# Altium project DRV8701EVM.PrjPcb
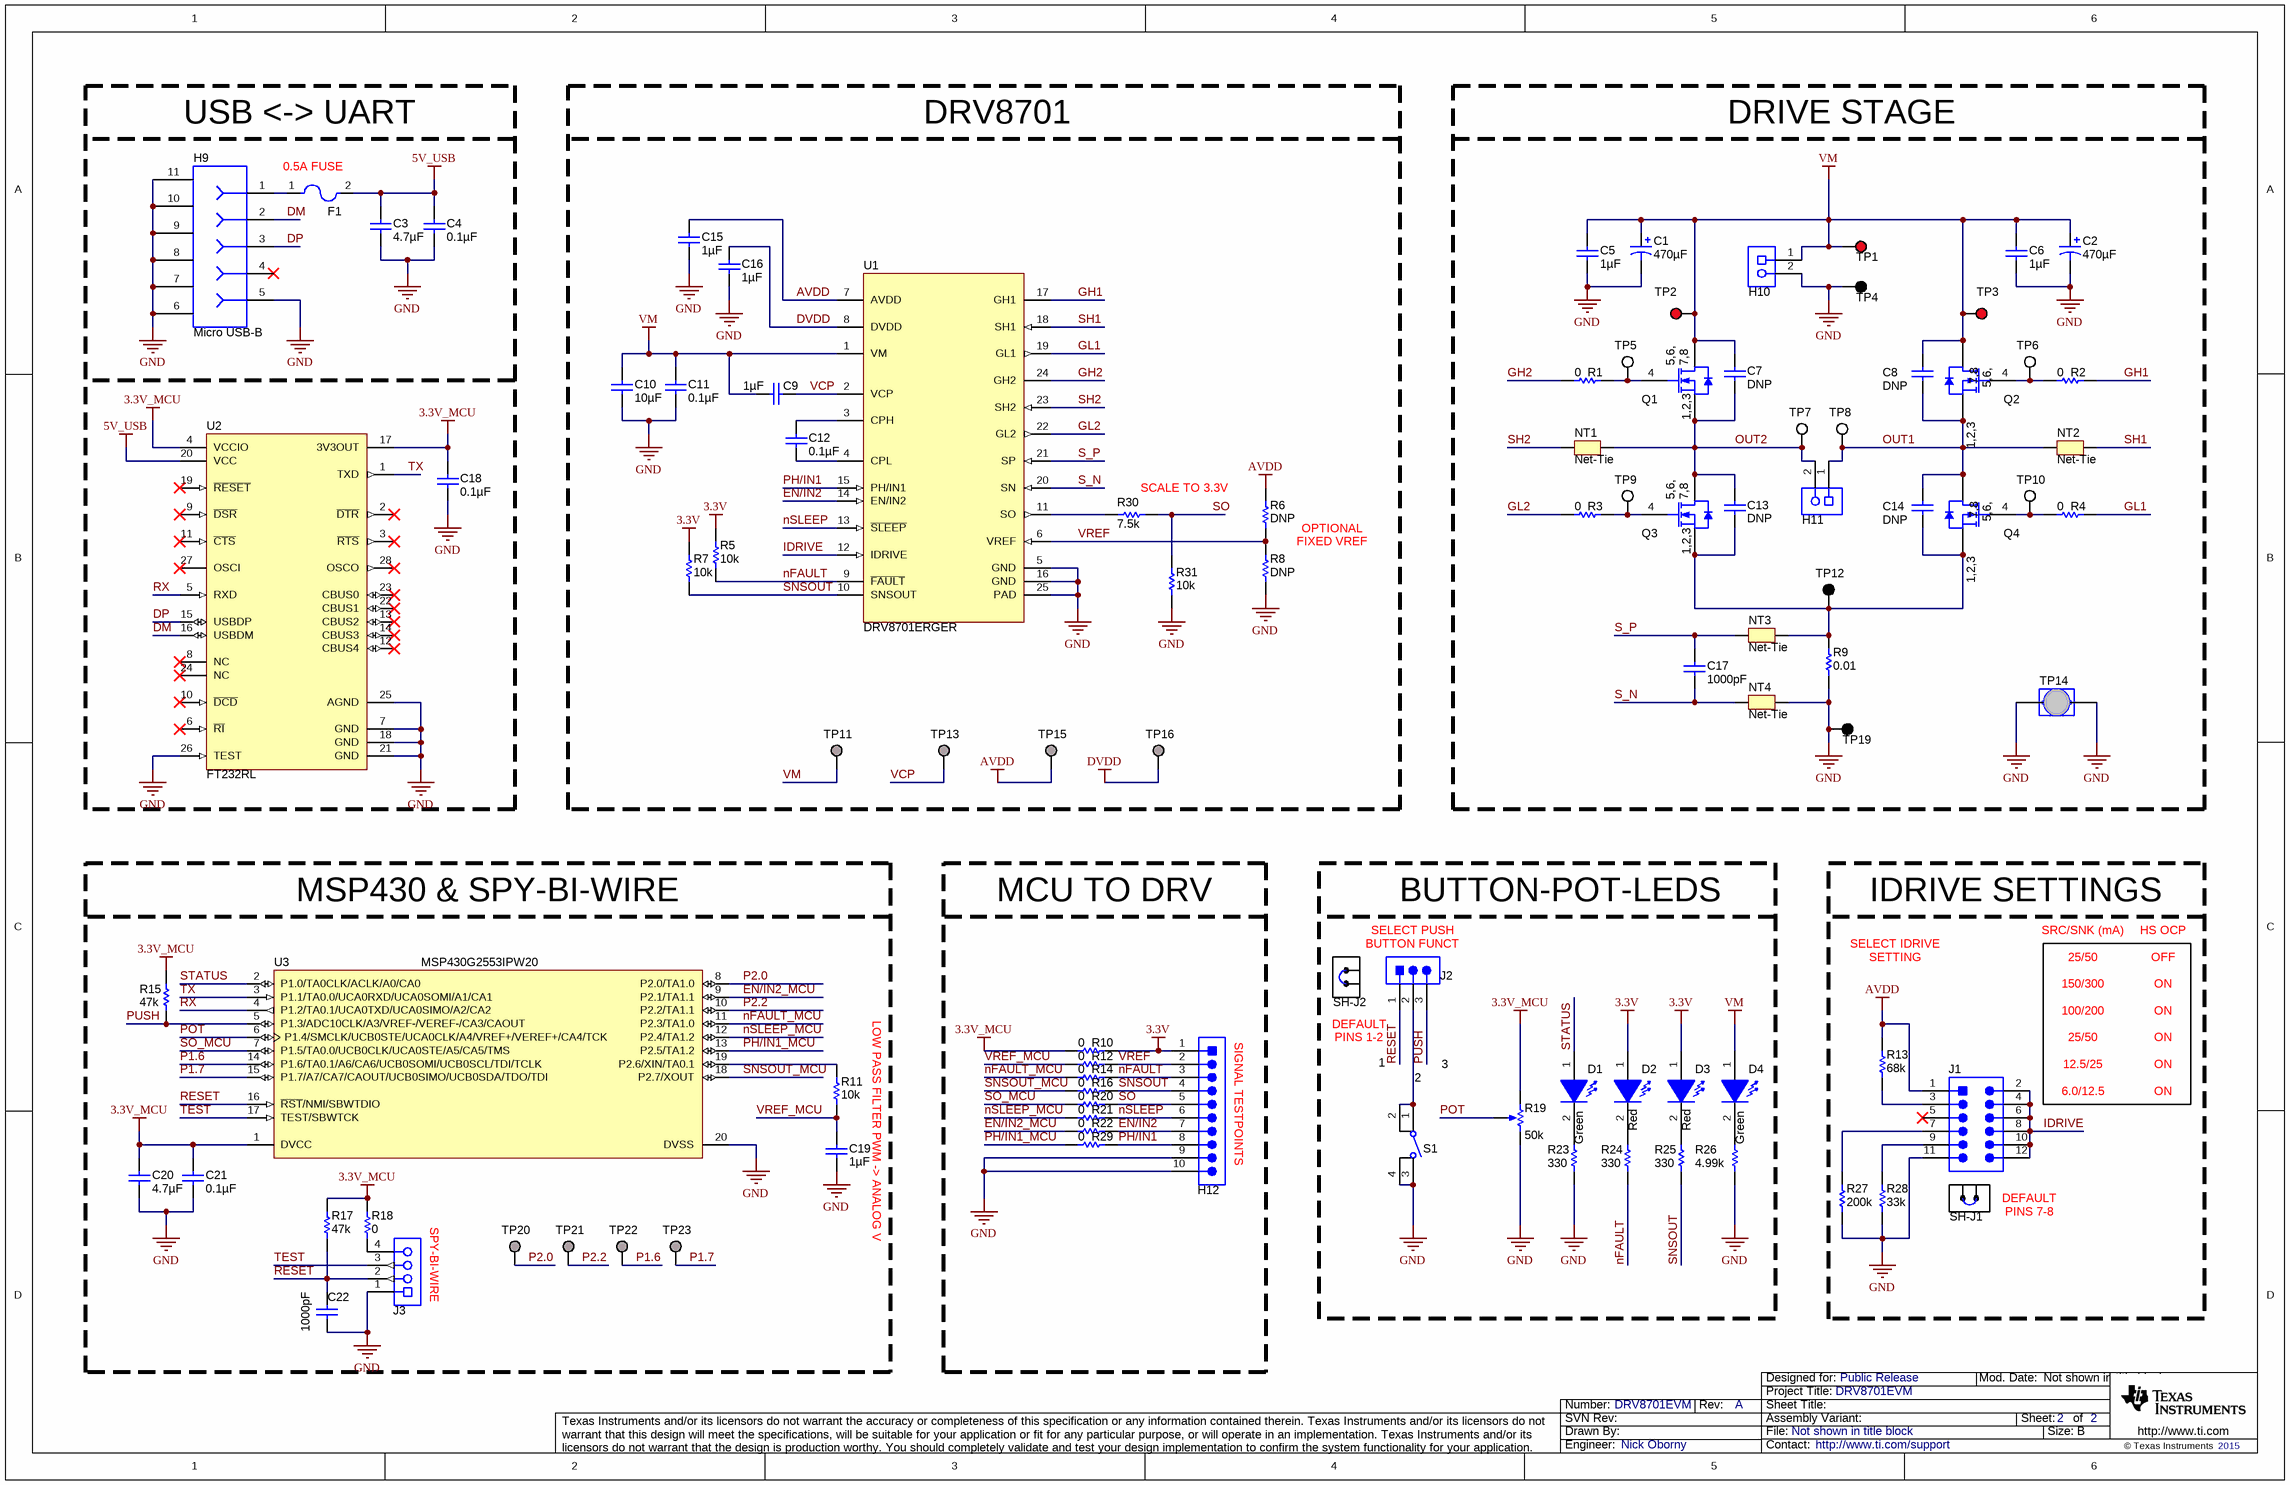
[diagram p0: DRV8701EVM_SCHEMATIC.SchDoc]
CopyrightYear: 2015; PCB_Layout: Nick Oborny; PCB_Rev: A; PRJ_Customer: Public Release; PRJ_Engineer: Nick Oborny; PRJ_Number: DRV8701EVM; PRJ_Title: DRV8701EVM; SCH_Rev: A; TechSupport: http://www.ti.com/support
2 sheets, 119 parts. Net scope: global (net labels, ports and power ports of the same name join across sheets).
Board file: DRV8701EVM.PcbDoc
Sheets:
  DRV8701EVM_SCHEMATIC.SchDoc
  DRV8701EVM_HARDWARE.SchDoc

## Sheet DRV8701EVM_SCHEMATIC.SchDoc
size 431 x 279 mm; Date: Not shown in title block; ApprovedBy: Not shown in title block; CheckedBy: Not shown in title block; Author: Not shown in title block; CompanyName: Not shown in title block; Engineer: Not shown in title block; Organization: Not shown in title block; Address1: Not shown in title block; Address2: Not shown in title block; Address3: Not shown in title block; Address4: Not shown in title block; DocumentNumber: 1; Revision: Use project parameter SCH_Rev; SheetNumber: 2; SheetTotal: 2; PageSetup: Record=PageOptions¦CenterHorizontal=True¦CenterVertical=True¦PrintScale=0.62¦XCorrection=1.00¦YCorrection=1.00¦PrintKind=0¦BorderSize=5000000¦LeftOffset=0¦BottomOffset=0¦Orientation=2¦PaperLength=1000¦PaperWidth=1000¦Scale=100¦PaperSource=15¦PrintQuality=600¦MediaType=1¦DitherType=10¦PaperKind=Letter¦PrintScaleMode=1

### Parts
C1  ValueDisplayed: 470µF  [M_1000x2000]  (hidden comment: ECA-1HM471)
C2  ValueDisplayed: 470µF  [M_1000x2000]  (hidden comment: ECA-1HM471)
C3  ValueDisplayed: 4.7µF  [0805L]  (hidden comment: C2012X7R1A475M)
C4  ValueDisplayed: 0.1µF  [0603L]  (hidden comment: C0603C104K8RACTU)
C5  ValueDisplayed: 1µF  [0805L]  (hidden comment: GRM21BR71H105KA12L)
C6  ValueDisplayed: 1µF  [0805L]  (hidden comment: GRM21BR71H105KA12L)
C7  DNP  [0603L]
C8  DNP  [0603L]
C9  ValueDisplayed: 1µF  [0603L]  (hidden comment: C1608X7R1C105K)
C10  ValueDisplayed: 10µF  [1210L]  (hidden comment: GRM32ER71H106KA12L)
C11  ValueDisplayed: 0.1µF  [0603L]  (hidden comment: C1608X7R1H104K)
C12  ValueDisplayed: 0.1µF  [0603L]  (hidden comment: C1608X7R1H104K)
C13  DNP  [0603L]
C14  DNP  [0603L]
C15  ValueDisplayed: 1µF  [0603L]  (hidden comment: GRM188R70J105KA01D)
C16  ValueDisplayed: 1µF  [0603L]  (hidden comment: GRM188R70J105KA01D)
C17  ValueDisplayed: 1000pF  [0402L]  (hidden comment: GRM155R71C102KA01D)
C18  ValueDisplayed: 0.1µF  [0603L]  (hidden comment: C0603C104K8RACTU)
C19  ValueDisplayed: 1µF  [0603L]  (hidden comment: GRM188R70J105KA01D)
C20  ValueDisplayed: 4.7µF  [0805L]  (hidden comment: C2012X7R1A475M)
C21  ValueDisplayed: 0.1µF  [0603L]  (hidden comment: C0603C104K8RACTU)
C22  ValueDisplayed: 1000pF  [0603L]  (hidden comment: GRM188R71C102KA01D)
D1  value Green  [LED_LTST-C171]  (hidden comment: LTST-C171GKT)
D2  value Red  [LED_LTST-C170]  (hidden comment: LTST-C170KRKT)
D3  value Red  [LED_LTST-C170]  (hidden comment: LTST-C170KRKT)
D4  value Green  [LED_LTST-C171]  (hidden comment: LTST-C171GKT)
F1  1206L050/15YR  [1206_FUSE]  (value not drawn)
H9  PackageReference: Micro USB-B  [CONN_USB_micro_ZX62-B-5PA]  (hidden comment: ZX62-B-5PA(11))
H10  691 101 710 002  [Wurth_691101710002]  (value not drawn)
H11  691 101 710 002  [Wurth_691101710002]  (value not drawn)
H12  TSW-110-07-G-S  [TSW-110-07-G-S]  (value not drawn)
J1  PEC06DAAN  [CONN_PEC06DAAN]  (value not drawn)
J2  PEC03SAAN  [CONN_PEC03SAAN]  (value not drawn)
J3  851-43-004-20-001000  [CONN_851-43-004-20-001000]  (value not drawn)
NT1  Net-Tie  [Net-Tie_10mil]  (net tie, no BOM)
NT2  Net-Tie  [Net-Tie_10mil]  (net tie, no BOM)
NT3  Net-Tie  [Net-Tie_10mil]  (net tie, no BOM)
NT4  Net-Tie  [Net-Tie_10mil]  (net tie, no BOM)
Q1  CSD18532Q5B  [TRANS_NexFET_Q5B]  (value not drawn)
Q2  CSD18532Q5B  [TRANS_NexFET_Q5B]  (value not drawn)
Q3  CSD18532Q5B  [TRANS_NexFET_Q5B]  (value not drawn)
Q4  CSD18532Q5B  [TRANS_NexFET_Q5B]  (value not drawn)
R1  value 0  [0603L]  (hidden comment: CRCW06030000Z0EA)
R2  value 0  [0603L]  (hidden comment: CRCW06030000Z0EA)
R3  value 0  [0603L]  (hidden comment: CRCW06030000Z0EA)
R4  value 0  [0603L]  (hidden comment: CRCW06030000Z0EA)
R5  value 10k  [0603L]  (hidden comment: CRCW060310K0JNEA)
R6  DNP  [0603L]
R7  value 10k  [0603L]  (hidden comment: CRCW060310K0JNEA)
R8  DNP  [0603L]
R9  value 0.01  [2512M]  (hidden comment: CRA2512-FZ-R010ELF)
R10  value 0  [0603L]  (hidden comment: CRCW06030000Z0EA)
R11  value 10k  [0603L]  (hidden comment: CRCW060310K0JNEA)
R12  value 0  [0603L]  (hidden comment: CRCW06030000Z0EA)
R13  value 68k  [0603L]  (hidden comment: CRCW060368K0JNEA)
R14  value 0  [0603L]  (hidden comment: CRCW06030000Z0EA)
R15  value 47k  [0603L]  (hidden comment: CRCW060347K0JNEA)
R16  value 0  [0603L]  (hidden comment: CRCW06030000Z0EA)
R17  value 47k  [0603L]  (hidden comment: CRCW060347K0JNEA)
R18  value 0  [0603L]  (hidden comment: CRCW06030000Z0EA)
R19  value 50k  [Bourns_3352T]  (hidden comment: 3352T-1-503LF)
R20  value 0  [0603L]  (hidden comment: CRCW06030000Z0EA)
R21  value 0  [0603L]  (hidden comment: CRCW06030000Z0EA)
R22  value 0  [0603L]  (hidden comment: CRCW06030000Z0EA)
R23  value 330  [0603L]  (hidden comment: CRCW0603330RJNEA)
R24  value 330  [0603L]  (hidden comment: CRCW0603330RJNEA)
R25  value 330  [0603L]  (hidden comment: CRCW0603330RJNEA)
R26  value 4.99k  [0603L]  (hidden comment: CRCW06034K99FKEA)
R27  value 200k  [0603L]  (hidden comment: CRCW0603200KJNEA)
R28  value 33k  [0603L]  (hidden comment: CRCW060333K0JNEA)
R29  value 0  [0603L]  (hidden comment: CRCW06030000Z0EA)
R30  ValueDisplayed: 7.5k  [0603L]  (hidden comment: CRCW06037K50JNEA)
R31  ValueDisplayed: 10k  [0603L]  (hidden comment: CRCW060310K0JNEA)
S1  4-1437565-1  [SW_FSM4JSMA]  (value not drawn)
SH-J1  969102-0000-DA  [SNT-100-BK-G]  (value not drawn)
SH-J2  969102-0000-DA  [SNT-100-BK-G]  (value not drawn)
TP1  5005  [Keystone5005]  (value not drawn)
TP2  5005  [Keystone5005]  (value not drawn)
TP3  5005  [Keystone5005]  (value not drawn)
TP4  5006  [Keystone5006]  (value not drawn)
TP5  5007  [Keystone5007]  (value not drawn)
TP6  5007  [Keystone5007]  (value not drawn)
TP7  5007  [Keystone5007]  (value not drawn)
TP8  5007  [Keystone5007]  (value not drawn)
TP9  5007  [Keystone5007]  (value not drawn)
TP10  5007  [Keystone5007]  (value not drawn)
TP11  VM  [TP_VIA_018RND008]  (value not drawn)  (no BOM)
TP12  5006  [Keystone5006]  (value not drawn)
TP13  VCP  [TP_VIA_018RND008]  (value not drawn)  (no BOM)
TP14  D3082-05  [Harwin_D3082-05]  (value not drawn)
TP15  AVDD  [TP_VIA_018RND008]  (value not drawn)  (no BOM)
TP16  DVDD  [TP_VIA_018RND008]  (value not drawn)  (no BOM)
TP19  5006  [Keystone5006]  (value not drawn)
TP20  TESTPOINT  [TP_VIA_060RND040]  (value not drawn)  (no BOM)
TP21  TESTPOINT  [TP_VIA_060RND040]  (value not drawn)  (no BOM)
TP22  TESTPOINT  [TP_VIA_060RND040]  (value not drawn)  (no BOM)
TP23  TESTPOINT  [TP_VIA_060RND040]  (value not drawn)  (no BOM)
U1  DRV8701ERGER  [RGE0024F]
U2  FT232RL  [SSOP28_N]
U3  MSP430G2553IPW20  [PW0020A_N]

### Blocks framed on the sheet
USB <-> UART: C3 C4 C18 F1 H9 U2
DRV8701: C9-C12 C15 C16 R5-R8 R30 R31 TP11 TP13 TP15 TP16 U1
DRIVE STAGE: C1 C2 C5-C8 C13 C14 C17 H10 H11 NT1-NT4 Q1-Q4 R1-R4 R9 TP1-TP10 TP12 TP14 TP19
MSP430 & SPY-BI-WIRE: C19-C22 J3 R11 R15 R17 R18 TP20-TP23 U3
MCU TO DRV: H12 R10 R12 R14 R16 R20-R22 R29
BUTTON-POT-LEDS: D1-D4 J2 R19 R23-R26 S1 SH-J2
IDRIVE SETTINGS: J1 R13 R27 R28 SH-J1

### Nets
3.3V: D2.1(A) D3.1(A) H12.1 R5.1 R7.1 R10.1
3.3V_MCU: C18.1 C20.1 C21.1 R10.2 R15.2 R17.2 R18.2 R19.1(CCW) U2.4(VCCIO) U2.17(3V3OUT) U3.1(DVCC)
5V_USB: C3.1 C4.1 F1.2 U2.20(VCC)
AVDD: C15.1 J1.1 R6.2 R13.2 TP15.1 U1.7(AVDD)
DVDD: C16.2 TP16.1 U1.8(DVDD)
GND: C1.2(-) C2.2(-) C3.2 C4.2 C5.2 C6.2 C10.2 C11.2 C15.2 C16.1 C18.2 C19.2 C20.2 C21.2 C22.2 H9.5 H9.6 H9.7 H9.8 H9.9 H9.10 H9.11 H10.2 H12.9 H12.10 J1.11 J3.1 NT4.2 R8.1 R9.1 R19.3(CW) R23.1 R26.1 R27.1 R28.1 R31.2 S1.3 S1.4 TP4.1 TP14.1 TP14.2 TP19.1 U1.5(GND) U1.16(GND) U1.25(PAD) U2.7(GND) U2.18(GND) U2.21(GND) U2.25(AGND) U2.26(TEST) U3.20(DVSS)
VM: C1.1(+) C2.1(+) C5.1 C6.1 C7.1 C8.1 C9.2 C10.1 C11.1 D4.1(A) H10.1 Q1.5(D) Q1.6(D) Q1.7(D) Q1.8(D) Q2.5(D) Q2.6(D) Q2.7(D) Q2.8(D) TP1.1 TP2.1 TP3.1 TP11.1 U1.1(VM)
DM: H9.2 U2.16(USBDM)
DP: H9.3 U2.15(USBDP)
EN/IN2: H12.7 R22.1 U1.14(EN/IN2)
EN/IN2_MCU: R22.2 U3.9(P2.1/TA1.1)
GH1: R2.1 U1.17(GH1)
GH2: R1.2 U1.24(GH2)
GL1: R4.1 U1.19(GL1)
GL2: R3.2 U1.22(GL2)
IDRIVE: J1.2 J1.4 J1.6 J1.8 J1.10 J1.12 U1.12(IDRIVE)
nFAULT: H12.3 R5.2 R14.1 R24.1 U1.9(~{FAULT})
nFAULT_MCU: R14.2 U3.11(P2.3/TA1.0)
nSLEEP: H12.6 R21.1 U1.13(~{SLEEP})
nSLEEP_MCU: R21.2 U3.12(P2.4/TA1.2)
OUT1: C8.2 C14.1 H11.1 NT2.2 Q2.1(S) Q2.2(S) Q2.3(S) Q4.5(D) Q4.6(D) Q4.7(D) Q4.8(D) TP8.1
OUT2: C7.2 C13.1 H11.2 NT1.2 Q1.1(S) Q1.2(S) Q1.3(S) Q3.5(D) Q3.6(D) Q3.7(D) Q3.8(D) TP7.1
P1.6: TP22.1 U3.14(P1.6/TA0.1/A6/CA6/UCB0SOMI/UCB0SCL/TDI/TCLK)
P1.7: TP23.1 U3.15(P1.7/A7/CA7/CAOUT/UCB0SIMO/UCB0SDA/TDO/TDI)
P2.0: TP20.1 U3.8(P2.0/TA1.0)
P2.2: TP21.1 U3.10(P2.2/TA1.1)
PH/IN1: H12.8 R29.1 U1.15(PH/IN1)
PH/IN1_MCU: R29.2 U3.13(P2.5/TA1.2)
POT: R19.2(WIPER) U3.6(P1.4/SMCLK/UCB0STE/UCA0CLK/A4/VREF+/VEREF+/CA4/TCK)
PUSH: J2.3 R15.1 U3.5(P1.3/ADC10CLK/A3/VREF-/VEREF-/CA3/CAOUT)
RESET: C22.1 J2.1 J3.2 R17.1 U3.16(~{RST}/NMI/SBWTDIO)
RX: U2.5(RXD) U3.4(P1.2/TA0.1/UCA0TXD/UCA0SIMO/A2/CA2)
S_N: C17.2 NT4.1 U1.20(SN)
S_P: C17.1 NT3.2 U1.21(SP)
SH1: NT2.1 U1.18(SH1)
SH2: NT1.1 U1.23(SH2)
SNSOUT: H12.4 R7.2 R16.1 R25.1 U1.10(SNSOUT)
SNSOUT_MCU: R16.2 U3.18(P2.7/XOUT)
SO: H12.5 R20.1 R30.1 R31.1
SO_MCU: R20.2 U3.7(P1.5/TA0.0/UCB0CLK/UCA0STE/A5/CA5/TMS)
STATUS: D1.1(A) U3.2(P1.0/TA0CLK/ACLK/A0/CA0)
TEST: J3.3 U3.17(TEST/SBWTCK)
TX: U2.1(TXD) U3.3(P1.1/TA0.0/UCA0RXD/UCA0SOMI/A1/CA1)
VCP: C9.1 TP13.1 U1.2(VCP)
VREF: H12.2 R6.1 R8.2 R12.1 U1.6(VREF)
VREF_MCU: C19.1 R11.2 R12.2
NetC12_1: C12.1 U1.3(CPH)
NetC12_2: C12.2 U1.4(CPL)
NetC13_2: C13.2 C14.2 NT3.1 Q3.1(S) Q3.2(S) Q3.3(S) Q4.1(S) Q4.2(S) Q4.3(S) R9.2 TP12.1
NetD1_2: D1.2(K) R23.2
NetD2_2: D2.2(K) R24.2
NetD3_2: D3.2(K) R25.2
NetD4_2: D4.2(K) R26.2
NetF1_1: F1.1 H9.1
NetJ1_3: J1.3 R13.1
NetJ1_7: J1.7 R27.2
NetJ1_9: J1.9 R28.2
NetJ2_2: J2.2 S1.1 S1.2
NetJ3_4: J3.4 R18.1
NetQ1_4: Q1.4(G) R1.1 TP5.1
NetQ2_4: Q2.4(G) R2.2 TP6.1
NetQ3_4: Q3.4(G) R3.1 TP9.1
NetQ4_4: Q4.4(G) R4.2 TP10.1
NetR11_1: R11.1 U3.19(P2.6/XIN/TA0.1)
NetR30_2: R30.2 U1.11(SO)

Not connected (* = marked no-connect by the designer): H9 4*; J1 5*; U2 2(~{DTR})* 3(~{RTS})* 6(~{RI})* 8(NC)* 9(~{DSR})* 10(~{DCD})* 11(~{CTS})* 12(CBUS4)* 13(CBUS2)* 14(CBUS3)* 19(~{RESET})* 22(CBUS1)* 23(CBUS0)* 24(NC)* 27(OSCI)* 28(OSCO)*

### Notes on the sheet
- (near F1) 0.5A FUSE
- (near R30) SCALE TO 3.3V
- OPTIONAL
- FIXED VREF
- SELECT PUSH
- BUTTON FUNCT
- SETTING
- SELECT IDRIVE
- SRC/SNK (mA)
- 25/50
- HS OCP
- OFF
- DEFAULT
- PINS 1-2
- 100/200
- 150/300
- ON
- (near H12) SIGNAL TESTPOINTS
- 1
- (near S1) 2
- 3
- 6.0/12.5
- 12.5/25
- LOW PASS FILTER PWM -> ANALOG V
- PINS 7-8
- (near J3) SPY-BI-WIRE

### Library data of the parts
C1 C2 = ECA-1HM471: CAP, AL, 470 µF, 50 V, +/- 20%,  ohm, TH; Manufacturer: Panasonic; Polarized: Y; CompType: Capacitor; Value: 470uF; U/M: EA; Cap_F: 0.00047; Tolerance_%: 20; Value1: Unknown; VDC_V: 50; Value2: 50V; IRMS_A: 0.65; TaMin_C: -40; TaMax_C: 85; Cap_Case: 10x20mm
C3 C20 = C2012X7R1A475M: CAP, CERM, 4.7uF, 10V, +/-20%, X7R, 0805; Manufacturer: TDK; Polarized: N; CompType: Capacitor; U/M: EA; Cap_F: 0.0000047; Tolerance_%: 20; Value1: Unknown; VDC_V: 10; TaMin_C: -55; TaMax_C: 125; Cap_Case: 0805
C4 C18 C21 = C0603C104K8RACTU: CAP, CERM, 0.1uF, 10V, +/-10%, X7R, 0603; Manufacturer: Kemet; Polarized: N; CompType: Capacitor; U/M: EA; Cap_F: 0.0000001; Tolerance_%: 10; Value1: Unknown; TaMin_C: -55; TaMax_C: 125; Cap_Case: 0603
C5 C6 = GRM21BR71H105KA12L: CAP, CERM, 1uF, 50V, +/-10%, X7R, 0805; Manufacturer: MuRata; Polarized: N; CompType: Capacitor; U/M: EA; Cap_F: 0.000001; Tolerance_%: 10; Value1: Unknown; VDC_V: 50; TaMin_C: -55; TaMax_C: 125; Cap_Case: 0805
C7 C8 C13 C14 = C1608X7R1H103K: CAP, CERM, 0.01uF, 50V, +/-10%, X7R, 0603; Polarized: N; CompType: Capacitor; U/M: EA; Cap_F: 0.00000001; Cap_Case: 0603
C9 = C1608X7R1C105K: CAP, CERM, 1uF, 16V, +/-10%, X7R, 0603; Manufacturer: TDK; Polarized: N; CompType: Capacitor; U/M: EA; Cap_F: 0.000001; Tolerance_%: 10; ESR_Ohm: 0.0057; Value1: 0.0057 ohm; VDC_V: 16; TaMin_C: -55; TaMax_C: 125; Cap_Case: 0603
C10 = GRM32ER71H106KA12L: CAP, CERM, 10uF, 50V, +/-10%, X7R, 1210; Manufacturer: MuRata; Polarized: N; CompType: Capacitor; U/M: EA; Cap_F: 0.00001; Tolerance_%: 10; Value1: Unknown; VDC_V: 50; TaMin_C: -55; TaMax_C: 125; Cap_Case: 1210
C11 C12 = C1608X7R1H104K: CAP, CERM, 0.1uF, 50V, +/-10%, X7R, 0603; Manufacturer: TDK; Polarized: N; CompType: Capacitor; U/M: EA; Cap_F: 0.0000001; Tolerance_%: 10; ESR_Ohm: 0.017; Value1: 0.017 ohm; VDC_V: 50; TaMin_C: -55; TaMax_C: 125; Cap_Case: 0603
C15 C16 C19 = GRM188R70J105KA01D: CAP, CERM, 1uF, 6.3V, +/-10%, X7R, 0603; Manufacturer: MuRata; Polarized: N; CompType: Capacitor; U/M: EA; Cap_F: 0.000001; Tolerance_%: 10; Value1: Unknown; VDC_V: 6.3; TaMin_C: -55; TaMax_C: 125; Cap_Case: 0603
C17 = GRM155R71C102KA01D: CAP, CERM, 1000pF, 16V, +/-10%, X7R, 0402; Manufacturer: MuRata; Polarized: N; CompType: Capacitor; U/M: EA; Cap_F: 0.000000001; Tolerance_%: 10; Value1: Unknown; VDC_V: 16; TaMin_C: -55; TaMax_C: 125; Cap_Case: 0402
C22 = GRM188R71C102KA01D: CAP, CERM, 1000pF, 16V, +/-10%, X7R, 0603; Manufacturer: MuRata; Polarized: N; CompType: Capacitor; U/M: EA; Cap_F: 0.000000001; Tolerance_%: 10; Value1: Unknown; VDC_V: 16; TaMin_C: -55; TaMax_C: 125; Cap_Case: 0603
D1 D4 = LTST-C171GKT: LED, Green, SMD; Manufacturer: Lite-On; Type: AlInGaP; Vf_V: 2.1; Value2: 2.1V; Io_A: 20; Value1: W; U/M: EA
D2 D3 = LTST-C170KRKT: LED, Red, SMD; Manufacturer: Lite-On; Type: AlInGaP; Vf_V: 2; Value2: 2V; Io_A: 20; Value1: W; U/M: EA
F1 = FUSE_1206L_SERIES: Fuse, Poly Resetable PTC, 0.5A; Manufacturer: Littelfuse; Area: 19800
H9 = ZX62-B-5PA(11): Connector, micro USB Type B, Receptacle, R/A, SMD; Manufacturer: Hirose Electric Co. Ltd.; SymbolCreator: a0411947; U/M: EA
H10 H11 = 691 101 710 002: Terminal Block, 5 mm, 2x1, Tin, TH; Manufacturer: Wurth Elektronik eiSos; SymbolCreator: a0412235; U/M: EA
H12 = TSW-110-07-G-S: Header, 100mil, 10x1, Gold, TH; Manufacturer: Samtec; SymbolCreator: a0412235; U/M: EA
J1 = PEC06DAAN: Header, 100mil, 6x2, Tin, TH; Manufacturer: Sullins Connector Solutions; SymbolCreator: a0412235; U/M: EA
J2 = PEC03SAAN: Header, 100mil, 3x1, Tin, TH; Manufacturer: Sullins Connector Solutions; SymbolCreator: a0799628; U/M: EA
J3 = 851-43-004-20-001000: SOCKET .050" GRID SIP 4 POS R/A, TH; Manufacturer: Mill-Max; SymbolCreator: a0411947; CompType: Header; U/M: EA
NT1-NT4 = Net-Tie: Single point connection between nets.; SymbolCreator: codlsc
Q1-Q4 = CSD18532Q5B: MOSFET, N-CH, 60V, 172A, SON 5x6mm; Manufacturer: Texas Instruments; Alternate Manufacturer: None; U/M: EA; ChType: N; VdsMax_V: 60; Value1: 3.3 ohm; Rdson45_Ohm: 3.3; Value2: 27 nC; QgTyp_nC: 27; Vgs_V: 1.6; IdsMax_A: 172
R1-R4 R10 R12 R14 R16 R18 R20-R22 R29 = CRCW06030000Z0EA: RES, 0 ohm, 5%, 0.1W, 0603; Manufacturer: Vishay-Dale; CompType: Resistor; Value_Code: 0000; Tolerance_%: 5; Power_W: 0.1; VDC_V: 75; TempCo: 200 ppm/C; EIA_Code: E24; U/M: EA
R5 R7 R11 = CRCW060310K0JNEA: RES, 10k ohm, 5%, 0.1W, 0603; Manufacturer: Vishay-Dale; CompType: Resistor; Res_ohm: 10000; Value_Code: 10k0; Tolerance_%: 5; Power_W: 0.1; VDC_V: 75; TempCo: 200 ppm/C; EIA_Code: E24; U/M: EA
R6 R8 = CRCW06030000Z0EA: RES, 0 ohm, 5%, 0.1W, 0603; CompType: Resistor; Power_W: 0.1; EIA_Code: E24; U/M: EA
R9 = CRA2512-FZ-R010ELF: RES, 0.01 ohm, 1%, 3W, 2512; Manufacturer: Bourns; CompType: Resistor; Value_Code: R010; Tolerance_%: 1; Power_W: 3; TempCo: 75 ppm/C; EIA_Code: E96; U/M: EA
R13 = CRCW060368K0JNEA: RES, 68k ohm, 5%, 0.1W, 0603; Manufacturer: Vishay-Dale; CompType: Resistor; Res_ohm: 68000; Value_Code: 68k0; Tolerance_%: 5; Power_W: 0.1; VDC_V: 75; TempCo: 200 ppm/C; EIA_Code: E24; U/M: EA
R15 R17 = CRCW060347K0JNEA: RES, 47k ohm, 5%, 0.1W, 0603; Manufacturer: Vishay-Dale; CompType: Resistor; Res_ohm: 47000; Value_Code: 47k0; Tolerance_%: 5; Power_W: 0.1; VDC_V: 75; TempCo: 200 ppm/C; EIA_Code: E24; U/M: EA
R19 = 3352T-1-503LF: Trimming Potentiometer, 50K, 0.5W, TH; Manufacturer: Bourns; Sim Note: Enter the Resistance value and the set point into parameter fields.; SymbolCreator: a0412235; CompType: Trimmer
R23-R25 = CRCW0603330RJNEA: RES, 330 ohm, 5%, 0.1W, 0603; Manufacturer: Vishay-Dale; CompType: Resistor; Value_Code: 330R; Tolerance_%: 5; Power_W: 0.1; VDC_V: 75; TempCo: 200 ppm/C; EIA_Code: E24; U/M: EA
R26 = CRCW06034K99FKEA: RES, 4.99k ohm, 1%, 0.1W, 0603; Manufacturer: Vishay-Dale; CompType: Resistor; Res_ohm: 4990; Value_Code: 4k99; Tolerance_%: 1; Power_W: 0.1; VDC_V: 75; TempCo: 100 ppm/C; EIA_Code: E96; U/M: EA
R27 = CRCW0603200KJNEA: RES, 200k ohm, 5%, 0.1W, 0603; Manufacturer: Vishay-Dale; CompType: Resistor; Res_ohm: 200000; Tolerance_%: 5; Power_W: 0.1; VDC_V: 75; TempCo: 200 ppm/C; EIA_Code: E24; U/M: EA
R28 = CRCW060333K0JNEA: RES, 33k ohm, 5%, 0.1W, 0603; Manufacturer: Vishay-Dale; CompType: Resistor; Res_ohm: 33000; Value_Code: 33k0; Tolerance_%: 5; Power_W: 0.1; VDC_V: 75; TempCo: 200 ppm/C; EIA_Code: E24; U/M: EA
R30 = CRCW06037K50JNEA: RES, 7.5 k, 5%, 0.1 W, 0603; Manufacturer: Vishay-Dale; CompType: Resistor; Value: 7.5k; Res_ohm: 7500; Value_Code: 7k50; Tolerance_%: 5; Power_W: 0.1; Value2: 0.1W; VDC_V: 75; TempCo: 200 ppm/C; EIA_Code: E24; U/M: EA
R31 = CRCW060310K0JNEA: RES, 10 k, 5%, 0.1 W, 0603; Manufacturer: Vishay-Dale; CompType: Resistor; Value: 10k; Res_ohm: 10000; Value_Code: 10k0; Tolerance_%: 5; Power_W: 0.1; Value2: 0.1W; VDC_V: 75; TempCo: 200 ppm/C; EIA_Code: E24; U/M: EA
S1 = 4-1437565-1: Switch, Tactile, SPST-NO, 0.05A, 12V, SMT; Manufacturer: TE Connectivity; SymbolCreator: a0412235; VDC_V: 12; SwitchFunction: Off-Mom; PositionCount: 1; CurrentRating_mA: 50
SH-J1 SH-J2 = 969102-0000-DA: Shunt, 100mil, Gold plated, Black; Manufacturer: 3M; Alternate Manufacturer: Samtec; Value: 1x2; Note: You can "mate" this to a header by matching the designator.  i.e. use SH-J3 for header J3
TP1-TP3 = 5005: Test Point, Compact, Red, TH; Manufacturer: Keystone; CompType: Test Point Loop; U/M: EA
TP4 TP12 TP19 = 5006: Test Point, Compact, Black, TH; Manufacturer: Keystone; CompType: Test Point Loop; U/M: EA
TP5-TP10 = 5007: Test Point, Compact, White, TH; Manufacturer: Keystone; CompType: Test Point Loop; U/M: EA
TP11 TP13 TP15 TP16 TP20-TP23 = TESTPOINT: TEST POINT.  No entry in BOM.
TP14 = D3082-05: 1mm Uninsulated Shorting Plug, 10.16mm spacing, TH; Manufacturer: Harwin; SymbolCreator: a0799628; CompType: Jumper Wire; U/M: EA
U1 = DRV8701ERGER: H-Bridge Gate Driver, RGE0024F; Alternate PartNumber: DRV8701ERGET; Manufacturer: Texas Instruments; SymbolCreator: Altium; CompType: IC; U/M: EA
U2 = FT232RL: USB to Serial UART, SSOP28; Manufacturer: FTDI; SymbolCreator: x0208326
U3 = MSP430G2553IPW20: 16 MHz Mixed Signal Microcontroller with 16 KB Flash, 512 B SRAM and 24 GPIOs, -40 to 85 degC, 20-pin SOP (PW), Green (RoHS & no Sb/Br); Alternate Manufacturer: Texas Instruments; Alternate PartNumber: Equivalent; ADC: 10-bit SAR; ADC Channels: 8; Brown Out Reset: Yes; Flash(KB): 16; GPIO: 24; Pin/Package: 0DIESALE, 0WAFERSALE, 20PDIP, 20TSSOP, 28TSSOP, 32QFN; SRAM(B): 512; SubFamily: Value Line; Timers - 16-bit: 2; USCI_A (UART/LIN/IrDA/SPI): 1

## Sheet DRV8701EVM_HARDWARE.SchDoc
size 431 x 279 mm; Date: Not shown in title block; ApprovedBy: Not shown in title block; CheckedBy: Not shown in title block; Author: Not shown in title block; CompanyName: Not shown in title block; Engineer: Not shown in title block; Organization: Not shown in title block; Address1: Not shown in title block; Address2: Not shown in title block; Address3: Not shown in title block; Address4: Not shown in title block; DocumentNumber: 1; Revision: Use project parameter SCH_Rev; SheetNumber: 1; SheetTotal: 1; PageSetup: Record=PageOptions|CenterHorizontal=True|CenterVertical=True|PrintScale=1.00|XCorrection=1.00|YCorrection=1.00|PrintKind=0|BorderSize=5000000|LeftOffset=0|BottomOffset=0|Orientation=2|PaperLength=1000|PaperWidth=1000|Scale=100|PaperSource=15|PrintQuality=600|MediaType=1|DitherType=10|PaperKind=Letter|PrintScaleMode=1
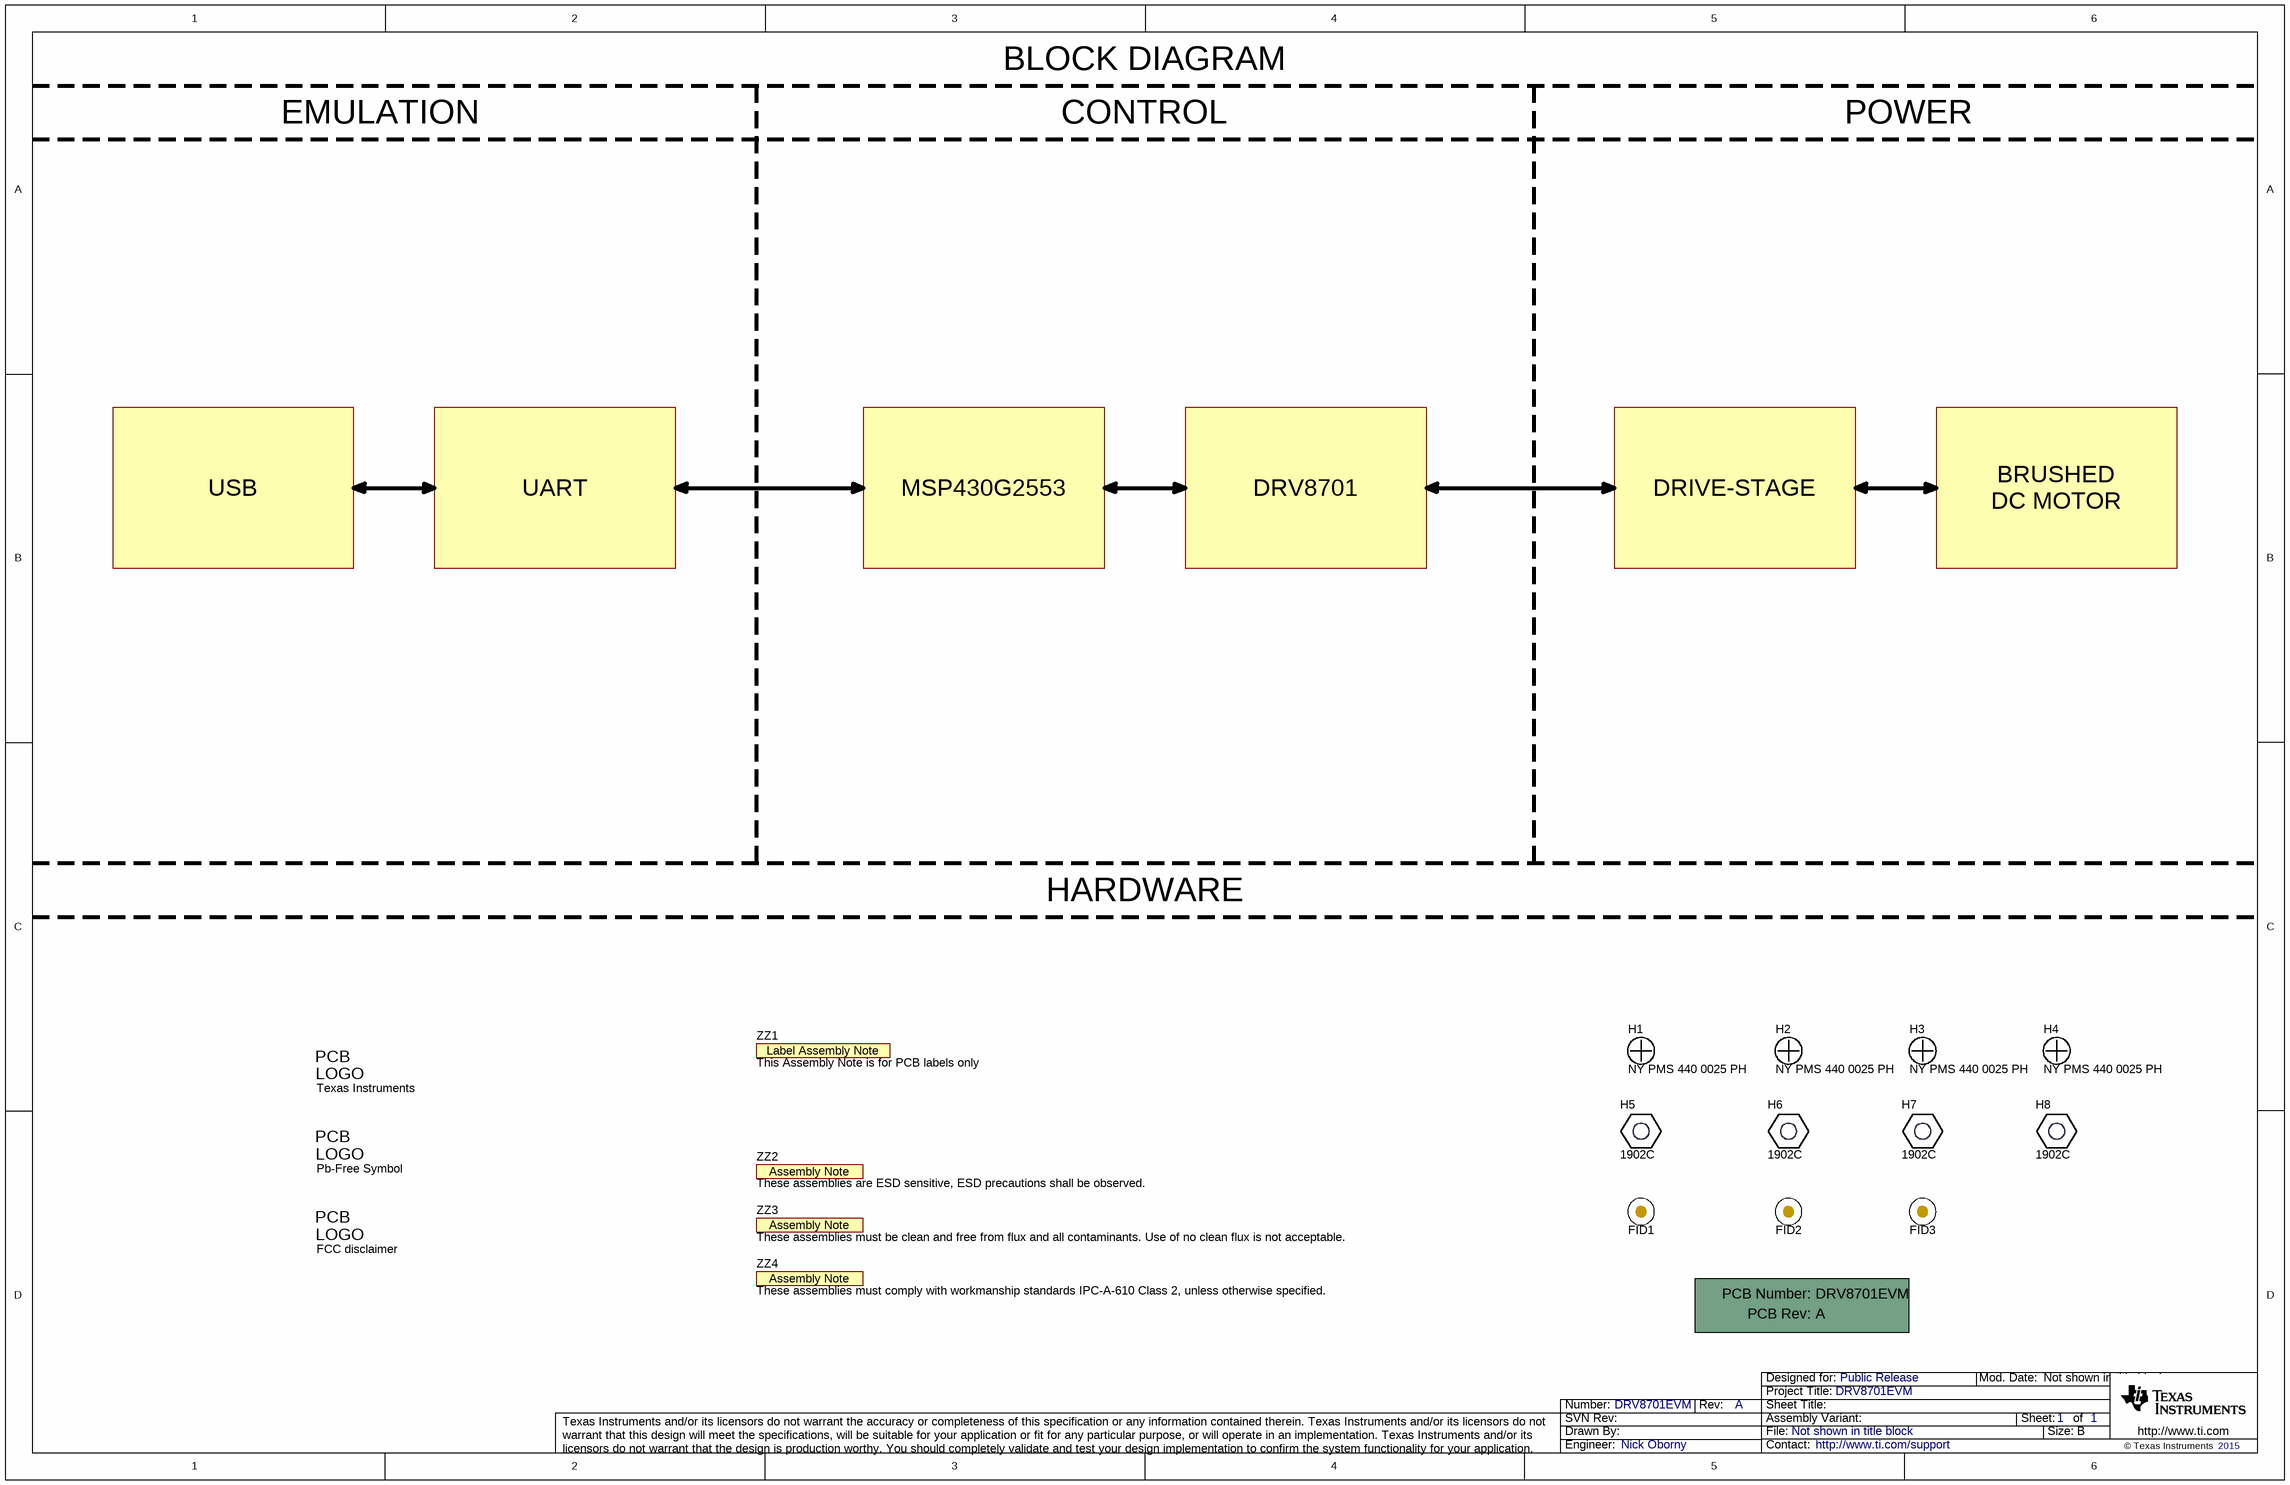
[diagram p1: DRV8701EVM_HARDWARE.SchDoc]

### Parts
!PCB1  Printed Circuit Board  (value not drawn)  (mechanical)
FID1  Fiducial  [Fiducial10-20]  (value not drawn)
FID2  Fiducial  [Fiducial10-20]  (value not drawn)
FID3  Fiducial  [Fiducial10-20]  (value not drawn)
H1  NY PMS 440 0025 PH  [NY PMS 440 0025 PH]
H2  NY PMS 440 0025 PH  [NY PMS 440 0025 PH]
H3  NY PMS 440 0025 PH  [NY PMS 440 0025 PH]
H4  NY PMS 440 0025 PH  [NY PMS 440 0025 PH]
H5  1902C  [Keystone_1902C]
H6  1902C  [Keystone_1902C]
H7  1902C  [Keystone_1902C]
H8  1902C  [Keystone_1902C]
Logo1  Texas Instruments  [TI_Stacked_Overlay_Small]  (no BOM)
Logo2  Pb-Free Symbol  [Pb-Free_Overlay_Medium]  (no BOM)
Logo3  FCC disclaimer  [FCC_disclaimer]  (no BOM)
ZZ1  This Assembly Note is for PCB labels only  [AssemblyNoteLabel]  (no BOM)
ZZ2  These assemblies are ESD sensitive, ESD precautions shall be observed.  [AssemblyNote]  (no BOM)
ZZ3  These assemblies must be clean and free from flux and all contaminants. Use of no clean flux is not acceptable.  [AssemblyNote]  (no BOM)
ZZ4  These assemblies must comply with workmanship standards IPC-A-610 Class 2, unless otherwise specified.  [AssemblyNote]  (no BOM)

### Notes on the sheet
- BLOCK DIAGRAM
- EMULATION
- CONTROL
- POWER
- USB
- UART
- MSP430G2553
- DRV8701
- DRIVE-STAGE
- BRUSHED
- DC MOTOR
- HARDWARE

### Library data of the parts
!PCB1 = PCB: Manufacturer: Any; PartNumber: DRV8701EVM; SymbolCreator: a0412235
FID1-FID3 = Fiducial: Fiducial mark.  There is nothing to buy or mount.; SymbolCreator: codlsc
H1-H4 = NY PMS 440 0025 PH: Machine Screw, Round, #4-40 x 1/4, Nylon, Philips panhead; Manufacturer: B&F Fastener Supply; CompType: Hardware; SymbolCreator: codlsc; U/M: EA
H5-H8 = 1902C: Standoff, Hex, 0.5"L #4-40 Nylon; Manufacturer: Keystone; CompType: Hardware
Logo1 = TI_Logo: Texas Instrument Corporate Signature; SymbolCreator: codlsc
Logo2 = Pb-Free: SymbolCreator: a0412235
Logo3 = FCC_disclaimer: SymbolCreator: codlsc
ZZ1 = AssemblyNoteLabel: SymbolCreator: a0412235
ZZ2-ZZ4 = AssemblyNote: SymbolCreator: codlsc

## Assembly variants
001: not fitted FID1 FID2 FID3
